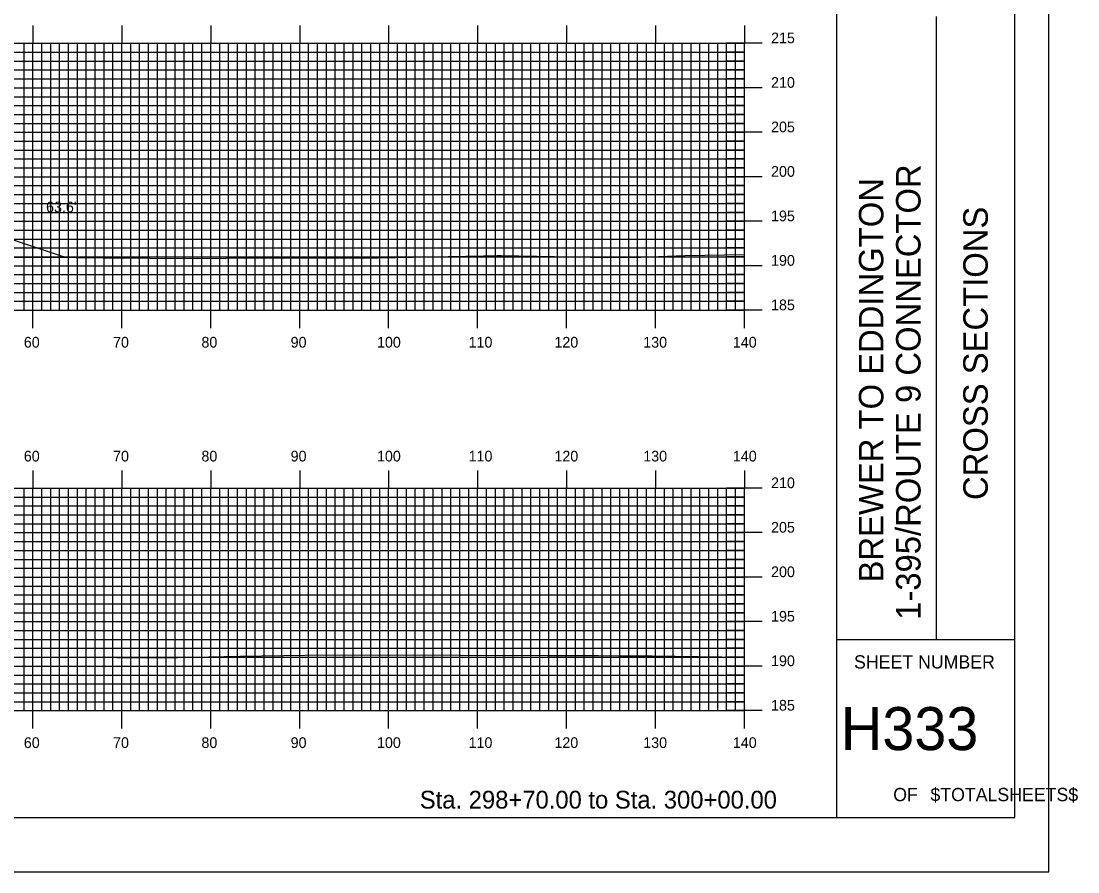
# Model space of a CAD drawing. Extents: x 1815309 to 1815652, y 442591 to 442811.
# Drawn here: x 1815533.2 to 1815652, y 442590.5 to 442686.2 of the extents above; entities that cross this region are included whole.
import ezdxf

# ---------------------------------------------------------------- set-up
doc = ezdxf.new("R2010")
doc.units = 0
for name, color, linetype in [('BORDER', 7, 'Continuous'), ('D_Roadway_Centerline', 7, 'Continuous'), ('D_Roadway_SlopeLines', 7, 'Continuous'), ('D_Text_Standard', 7, 'Continuous'), ('H_V ANNOTATION', 7, 'Continuous'), ('MAJOR', 7, 'Continuous'), ('MINOR', 7, 'Continuous'), ('PLOT BOUNDARY', 7, 'Continuous'), ('S_Roadway_Centerline', 7, 'Continuous')]:
    doc.layers.add(name, color=color, linetype=linetype)

msp = doc.modelspace()

# ---------------------------------------------------------------- linework, layer by layer
at = {"layer": 'BORDER'}
for p, q in [((1815624.93, 442596.67), (1815624.93, 442806.67)), ((1815636.12, 442616.67), (1815636.12, 442686.67)), ((1815624.93, 442616.67), (1815644.93, 442616.67))]:
    msp.add_line(p, q, dxfattribs=at)
msp.add_lwpolyline([(1815324.93, 442596.67), (1815644.93, 442596.67), (1815644.93, 442806.67), (1815324.93, 442806.67)], close=True, dxfattribs=at)
at = {"layer": 'D_Roadway_Centerline'}
msp.add_lwpolyline([(1815410.41, 442660.06), (1815442.53, 442670.77), (1815444.25, 442671.2), (1815454.53, 442673.77), (1815462.53, 442674.06), (1815474.53, 442673.77), (1815486.53, 442673.48), (1815494.53, 442673.16), (1815505.06, 442670.53), (1815506.53, 442670.16), (1815538.16, 442659.62)], dxfattribs=at)
at = {"layer": 'D_Roadway_SlopeLines'}
msp.add_lwpolyline([(1815494.53, 442673.16), (1815506.53, 442670.16), (1815538.16, 442659.62)], dxfattribs=at)
at = {"layer": 'MAJOR'}
for p, q in [((1815534.53, 442685.67), (1815534.53, 442683.67)), ((1815544.53, 442685.67), (1815544.53, 442683.67)), ((1815554.53, 442685.67), (1815554.53, 442683.67)), ((1815564.53, 442685.67), (1815564.53, 442683.67)), ((1815574.53, 442685.67), (1815574.53, 442683.67)), ((1815584.53, 442685.67), (1815584.53, 442683.67)), ((1815594.53, 442685.67), (1815594.53, 442683.67)), ((1815604.53, 442685.67), (1815604.53, 442683.67)), ((1815614.53, 442685.67), (1815614.53, 442683.67)), ((1815334.53, 442683.67), (1815614.53, 442683.67)), ((1815334.53, 442683.67), (1815614.53, 442683.67)), ((1815534.53, 442653.67), (1815534.53, 442683.67)), ((1815544.53, 442653.67), (1815544.53, 442683.67)), ((1815554.53, 442653.67), (1815554.53, 442683.67)), ((1815564.53, 442653.67), (1815564.53, 442683.67)), ((1815574.53, 442653.67), (1815574.53, 442683.67)), ((1815584.53, 442653.67), (1815584.53, 442683.67)), ((1815594.53, 442653.67), (1815594.53, 442683.67)), ((1815604.53, 442653.67), (1815604.53, 442683.67)), ((1815616.54, 442683.67), (1815612.53, 442683.67)), ((1815614.53, 442653.67), (1815614.53, 442683.67)), ((1815614.53, 442653.67), (1815614.53, 442683.67)), ((1815334.53, 442678.67), (1815614.53, 442678.67)), ((1815616.54, 442678.67), (1815612.53, 442678.67)), ((1815334.53, 442673.67), (1815614.53, 442673.67)), ((1815616.54, 442673.67), (1815612.53, 442673.67)), ((1815334.53, 442668.67), (1815614.53, 442668.67)), ((1815616.54, 442668.67), (1815612.53, 442668.67)), ((1815334.53, 442663.67), (1815614.53, 442663.67)), ((1815616.54, 442663.67), (1815612.53, 442663.67)), ((1815334.53, 442658.67), (1815614.53, 442658.67)), ((1815616.54, 442658.67), (1815612.53, 442658.67)), ((1815334.53, 442653.67), (1815614.53, 442653.67)), ((1815334.53, 442653.67), (1815614.53, 442653.67)), ((1815534.53, 442651.66), (1815534.53, 442653.67)), ((1815544.53, 442651.66), (1815544.53, 442653.67)), ((1815554.53, 442651.66), (1815554.53, 442653.67)), ((1815564.53, 442651.66), (1815564.53, 442653.67)), ((1815574.53, 442651.66), (1815574.53, 442653.67)), ((1815584.53, 442651.66), (1815584.53, 442653.67)), ((1815594.53, 442651.66), (1815594.53, 442653.67)), ((1815604.53, 442651.66), (1815604.53, 442653.67)), ((1815616.54, 442653.67), (1815612.53, 442653.67)), ((1815614.53, 442651.66), (1815614.53, 442653.67)), ((1815534.53, 442635.67), (1815534.53, 442633.67)), ((1815544.53, 442635.67), (1815544.53, 442633.67)), ((1815554.53, 442635.67), (1815554.53, 442633.67)), ((1815564.53, 442635.67), (1815564.53, 442633.67)), ((1815574.53, 442635.67), (1815574.53, 442633.67)), ((1815584.53, 442635.67), (1815584.53, 442633.67)), ((1815594.53, 442635.67), (1815594.53, 442633.67)), ((1815604.53, 442635.67), (1815604.53, 442633.67)), ((1815614.53, 442635.67), (1815614.53, 442633.67)), ((1815334.53, 442633.67), (1815614.53, 442633.67)), ((1815334.53, 442633.67), (1815614.53, 442633.67)), ((1815534.53, 442608.67), (1815534.53, 442633.67)), ((1815544.53, 442608.67), (1815544.53, 442633.67)), ((1815554.53, 442608.67), (1815554.53, 442633.67)), ((1815564.53, 442608.67), (1815564.53, 442633.67)), ((1815574.53, 442608.67), (1815574.53, 442633.67)), ((1815584.53, 442608.67), (1815584.53, 442633.67)), ((1815594.53, 442608.67), (1815594.53, 442633.67)), ((1815604.53, 442608.67), (1815604.53, 442633.67)), ((1815616.54, 442633.67), (1815612.53, 442633.67)), ((1815614.53, 442608.67), (1815614.53, 442633.67)), ((1815614.53, 442608.67), (1815614.53, 442633.67)), ((1815334.53, 442628.67), (1815614.53, 442628.67)), ((1815616.54, 442628.67), (1815612.53, 442628.67)), ((1815334.53, 442623.67), (1815614.53, 442623.67)), ((1815616.54, 442623.67), (1815612.53, 442623.67)), ((1815334.53, 442618.67), (1815614.53, 442618.67)), ((1815616.54, 442618.67), (1815612.53, 442618.67)), ((1815334.53, 442613.67), (1815614.53, 442613.67)), ((1815616.54, 442613.67), (1815612.53, 442613.67)), ((1815334.53, 442608.67), (1815614.53, 442608.67)), ((1815334.53, 442608.67), (1815614.53, 442608.67)), ((1815534.53, 442606.66), (1815534.53, 442608.67)), ((1815544.53, 442606.66), (1815544.53, 442608.67)), ((1815554.53, 442606.66), (1815554.53, 442608.67)), ((1815564.53, 442606.66), (1815564.53, 442608.67)), ((1815574.53, 442606.66), (1815574.53, 442608.67)), ((1815584.53, 442606.66), (1815584.53, 442608.67)), ((1815594.53, 442606.66), (1815594.53, 442608.67)), ((1815604.53, 442606.66), (1815604.53, 442608.67)), ((1815616.54, 442608.67), (1815612.53, 442608.67)), ((1815614.53, 442606.66), (1815614.53, 442608.67))]:
    msp.add_line(p, q, dxfattribs=at)
at = {"layer": 'MINOR'}
for p, q in [((1815533.53, 442653.67), (1815533.53, 442683.67)), ((1815535.53, 442653.67), (1815535.53, 442683.67)), ((1815536.53, 442653.67), (1815536.53, 442683.67)), ((1815537.53, 442653.67), (1815537.53, 442683.67)), ((1815538.53, 442653.67), (1815538.53, 442683.67)), ((1815539.53, 442653.67), (1815539.53, 442683.67)), ((1815540.53, 442653.67), (1815540.53, 442683.67)), ((1815541.53, 442653.67), (1815541.53, 442683.67)), ((1815542.53, 442653.67), (1815542.53, 442683.67)), ((1815543.53, 442653.67), (1815543.53, 442683.67)), ((1815545.53, 442653.67), (1815545.53, 442683.67)), ((1815546.53, 442653.67), (1815546.53, 442683.67)), ((1815547.53, 442653.67), (1815547.53, 442683.67)), ((1815548.53, 442653.67), (1815548.53, 442683.67)), ((1815549.53, 442653.67), (1815549.53, 442683.67)), ((1815550.53, 442653.67), (1815550.53, 442683.67)), ((1815551.53, 442653.67), (1815551.53, 442683.67)), ((1815552.53, 442653.67), (1815552.53, 442683.67)), ((1815553.53, 442653.67), (1815553.53, 442683.67)), ((1815555.53, 442653.67), (1815555.53, 442683.67)), ((1815556.53, 442653.67), (1815556.53, 442683.67)), ((1815557.53, 442653.67), (1815557.53, 442683.67)), ((1815558.53, 442653.67), (1815558.53, 442683.67)), ((1815559.53, 442653.67), (1815559.53, 442683.67)), ((1815560.53, 442653.67), (1815560.53, 442683.67)), ((1815561.53, 442653.67), (1815561.53, 442683.67)), ((1815562.53, 442653.67), (1815562.53, 442683.67)), ((1815563.53, 442653.67), (1815563.53, 442683.67)), ((1815565.53, 442653.67), (1815565.53, 442683.67)), ((1815566.53, 442653.67), (1815566.53, 442683.67)), ((1815567.53, 442653.67), (1815567.53, 442683.67)), ((1815568.53, 442653.67), (1815568.53, 442683.67)), ((1815569.53, 442653.67), (1815569.53, 442683.67)), ((1815570.53, 442653.67), (1815570.53, 442683.67)), ((1815571.53, 442653.67), (1815571.53, 442683.67)), ((1815572.53, 442653.67), (1815572.53, 442683.67)), ((1815573.53, 442653.67), (1815573.53, 442683.67)), ((1815575.53, 442653.67), (1815575.53, 442683.67)), ((1815576.53, 442653.67), (1815576.53, 442683.67)), ((1815577.53, 442653.67), (1815577.53, 442683.67)), ((1815578.53, 442653.67), (1815578.53, 442683.67)), ((1815579.53, 442653.67), (1815579.53, 442683.67)), ((1815580.53, 442653.67), (1815580.53, 442683.67)), ((1815581.53, 442653.67), (1815581.53, 442683.67)), ((1815582.53, 442653.67), (1815582.53, 442683.67)), ((1815583.53, 442653.67), (1815583.53, 442683.67)), ((1815585.53, 442653.67), (1815585.53, 442683.67)), ((1815586.53, 442653.67), (1815586.53, 442683.67)), ((1815587.53, 442653.67), (1815587.53, 442683.67)), ((1815588.53, 442653.67), (1815588.53, 442683.67)), ((1815589.53, 442653.67), (1815589.53, 442683.67)), ((1815590.53, 442653.67), (1815590.53, 442683.67)), ((1815591.53, 442653.67), (1815591.53, 442683.67)), ((1815592.53, 442653.67), (1815592.53, 442683.67)), ((1815593.53, 442653.67), (1815593.53, 442683.67)), ((1815595.53, 442653.67), (1815595.53, 442683.67)), ((1815596.53, 442653.67), (1815596.53, 442683.67)), ((1815597.53, 442653.67), (1815597.53, 442683.67)), ((1815598.53, 442653.67), (1815598.53, 442683.67)), ((1815599.53, 442653.67), (1815599.53, 442683.67)), ((1815600.53, 442653.67), (1815600.53, 442683.67)), ((1815601.53, 442653.67), (1815601.53, 442683.67)), ((1815602.53, 442653.67), (1815602.53, 442683.67)), ((1815603.53, 442653.67), (1815603.53, 442683.67)), ((1815605.53, 442653.67), (1815605.53, 442683.67)), ((1815606.53, 442653.67), (1815606.53, 442683.67)), ((1815607.53, 442653.67), (1815607.53, 442683.67)), ((1815608.53, 442653.67), (1815608.53, 442683.67)), ((1815609.53, 442653.67), (1815609.53, 442683.67)), ((1815610.53, 442653.67), (1815610.53, 442683.67)), ((1815611.53, 442653.67), (1815611.53, 442683.67)), ((1815612.53, 442653.67), (1815612.53, 442683.67)), ((1815613.53, 442653.67), (1815613.53, 442683.67)), ((1815334.53, 442682.67), (1815614.53, 442682.67)), ((1815614.53, 442682.67), (1815612.53, 442682.67)), ((1815334.53, 442681.67), (1815614.53, 442681.67)), ((1815614.53, 442681.67), (1815612.53, 442681.67)), ((1815334.53, 442680.67), (1815614.53, 442680.67)), ((1815614.53, 442680.67), (1815612.53, 442680.67)), ((1815334.53, 442679.67), (1815614.53, 442679.67)), ((1815614.53, 442679.67), (1815612.53, 442679.67)), ((1815334.53, 442677.67), (1815614.53, 442677.67)), ((1815614.53, 442677.67), (1815612.53, 442677.67)), ((1815334.53, 442676.67), (1815614.53, 442676.67)), ((1815614.53, 442676.67), (1815612.53, 442676.67)), ((1815334.53, 442675.67), (1815614.53, 442675.67)), ((1815614.53, 442675.67), (1815612.53, 442675.67)), ((1815334.53, 442674.67), (1815614.53, 442674.67)), ((1815614.53, 442674.67), (1815612.53, 442674.67)), ((1815334.53, 442672.67), (1815614.53, 442672.67)), ((1815614.53, 442672.67), (1815612.53, 442672.67)), ((1815334.53, 442671.67), (1815614.53, 442671.67)), ((1815614.53, 442671.67), (1815612.53, 442671.67)), ((1815334.53, 442670.67), (1815614.53, 442670.67)), ((1815614.53, 442670.67), (1815612.53, 442670.67)), ((1815334.53, 442669.67), (1815614.53, 442669.67)), ((1815614.53, 442669.67), (1815612.53, 442669.67)), ((1815334.53, 442667.67), (1815614.53, 442667.67)), ((1815334.53, 442666.67), (1815614.53, 442666.67)), ((1815614.53, 442667.67), (1815612.53, 442667.67)), ((1815614.53, 442666.67), (1815612.53, 442666.67)), ((1815334.53, 442665.67), (1815614.53, 442665.67)), ((1815614.53, 442665.67), (1815612.53, 442665.67)), ((1815334.53, 442664.67), (1815614.53, 442664.67)), ((1815614.53, 442664.67), (1815612.53, 442664.67)), ((1815334.53, 442662.67), (1815614.53, 442662.67)), ((1815614.53, 442662.67), (1815612.53, 442662.67)), ((1815334.53, 442661.67), (1815614.53, 442661.67)), ((1815334.53, 442660.67), (1815614.53, 442660.67)), ((1815614.53, 442661.67), (1815612.53, 442661.67)), ((1815614.53, 442660.67), (1815612.53, 442660.67)), ((1815334.53, 442659.67), (1815614.53, 442659.67)), ((1815614.53, 442659.67), (1815612.53, 442659.67)), ((1815334.53, 442657.67), (1815614.53, 442657.67)), ((1815614.53, 442657.67), (1815612.53, 442657.67)), ((1815334.53, 442656.67), (1815614.53, 442656.67)), ((1815614.53, 442656.67), (1815612.53, 442656.67)), ((1815334.53, 442655.67), (1815614.53, 442655.67)), ((1815614.53, 442655.67), (1815612.53, 442655.67)), ((1815334.53, 442654.67), (1815614.53, 442654.67)), ((1815614.53, 442654.67), (1815612.53, 442654.67)), ((1815533.53, 442608.67), (1815533.53, 442633.67)), ((1815535.53, 442608.67), (1815535.53, 442633.67)), ((1815536.53, 442608.67), (1815536.53, 442633.67)), ((1815537.53, 442608.67), (1815537.53, 442633.67)), ((1815538.53, 442608.67), (1815538.53, 442633.67)), ((1815539.53, 442608.67), (1815539.53, 442633.67)), ((1815540.53, 442608.67), (1815540.53, 442633.67)), ((1815541.53, 442608.67), (1815541.53, 442633.67)), ((1815542.53, 442608.67), (1815542.53, 442633.67)), ((1815543.53, 442608.67), (1815543.53, 442633.67)), ((1815545.53, 442608.67), (1815545.53, 442633.67)), ((1815546.53, 442608.67), (1815546.53, 442633.67)), ((1815547.53, 442608.67), (1815547.53, 442633.67)), ((1815548.53, 442608.67), (1815548.53, 442633.67)), ((1815549.53, 442608.67), (1815549.53, 442633.67)), ((1815550.53, 442608.67), (1815550.53, 442633.67)), ((1815551.53, 442608.67), (1815551.53, 442633.67)), ((1815552.53, 442608.67), (1815552.53, 442633.67)), ((1815553.53, 442608.67), (1815553.53, 442633.67)), ((1815555.53, 442608.67), (1815555.53, 442633.67)), ((1815556.53, 442608.67), (1815556.53, 442633.67)), ((1815557.53, 442608.67), (1815557.53, 442633.67)), ((1815558.53, 442608.67), (1815558.53, 442633.67)), ((1815559.53, 442608.67), (1815559.53, 442633.67)), ((1815560.53, 442608.67), (1815560.53, 442633.67)), ((1815561.53, 442608.67), (1815561.53, 442633.67)), ((1815562.53, 442608.67), (1815562.53, 442633.67)), ((1815563.53, 442608.67), (1815563.53, 442633.67)), ((1815565.53, 442608.67), (1815565.53, 442633.67)), ((1815566.53, 442608.67), (1815566.53, 442633.67)), ((1815567.53, 442608.67), (1815567.53, 442633.67)), ((1815568.53, 442608.67), (1815568.53, 442633.67)), ((1815569.53, 442608.67), (1815569.53, 442633.67)), ((1815570.53, 442608.67), (1815570.53, 442633.67)), ((1815571.53, 442608.67), (1815571.53, 442633.67)), ((1815572.53, 442608.67), (1815572.53, 442633.67)), ((1815573.53, 442608.67), (1815573.53, 442633.67)), ((1815575.53, 442608.67), (1815575.53, 442633.67)), ((1815576.53, 442608.67), (1815576.53, 442633.67)), ((1815577.53, 442608.67), (1815577.53, 442633.67)), ((1815578.53, 442608.67), (1815578.53, 442633.67)), ((1815579.53, 442608.67), (1815579.53, 442633.67)), ((1815580.53, 442608.67), (1815580.53, 442633.67)), ((1815581.53, 442608.67), (1815581.53, 442633.67)), ((1815582.53, 442608.67), (1815582.53, 442633.67)), ((1815583.53, 442608.67), (1815583.53, 442633.67)), ((1815585.53, 442608.67), (1815585.53, 442633.67)), ((1815586.53, 442608.67), (1815586.53, 442633.67)), ((1815587.53, 442608.67), (1815587.53, 442633.67)), ((1815588.53, 442608.67), (1815588.53, 442633.67)), ((1815589.53, 442608.67), (1815589.53, 442633.67)), ((1815590.53, 442608.67), (1815590.53, 442633.67)), ((1815591.53, 442608.67), (1815591.53, 442633.67)), ((1815592.53, 442608.67), (1815592.53, 442633.67)), ((1815593.53, 442608.67), (1815593.53, 442633.67)), ((1815595.53, 442608.67), (1815595.53, 442633.67)), ((1815596.53, 442608.67), (1815596.53, 442633.67)), ((1815597.53, 442608.67), (1815597.53, 442633.67)), ((1815598.53, 442608.67), (1815598.53, 442633.67)), ((1815599.53, 442608.67), (1815599.53, 442633.67)), ((1815600.53, 442608.67), (1815600.53, 442633.67)), ((1815601.53, 442608.67), (1815601.53, 442633.67)), ((1815602.53, 442608.67), (1815602.53, 442633.67)), ((1815603.53, 442608.67), (1815603.53, 442633.67)), ((1815605.53, 442608.67), (1815605.53, 442633.67)), ((1815606.53, 442608.67), (1815606.53, 442633.67)), ((1815607.53, 442608.67), (1815607.53, 442633.67)), ((1815608.53, 442608.67), (1815608.53, 442633.67)), ((1815609.53, 442608.67), (1815609.53, 442633.67)), ((1815610.53, 442608.67), (1815610.53, 442633.67)), ((1815611.53, 442608.67), (1815611.53, 442633.67)), ((1815612.53, 442608.67), (1815612.53, 442633.67)), ((1815613.53, 442608.67), (1815613.53, 442633.67)), ((1815334.53, 442632.67), (1815614.53, 442632.67)), ((1815614.53, 442632.67), (1815612.53, 442632.67)), ((1815334.53, 442631.67), (1815614.53, 442631.67)), ((1815614.53, 442631.67), (1815612.53, 442631.67)), ((1815334.53, 442630.67), (1815614.53, 442630.67)), ((1815614.53, 442630.67), (1815612.53, 442630.67)), ((1815334.53, 442629.67), (1815614.53, 442629.67)), ((1815614.53, 442629.67), (1815612.53, 442629.67)), ((1815334.53, 442627.67), (1815614.53, 442627.67)), ((1815614.53, 442627.67), (1815612.53, 442627.67)), ((1815334.53, 442626.67), (1815614.53, 442626.67)), ((1815614.53, 442626.67), (1815612.53, 442626.67)), ((1815334.53, 442625.67), (1815614.53, 442625.67)), ((1815614.53, 442625.67), (1815612.53, 442625.67)), ((1815334.53, 442624.67), (1815614.53, 442624.67)), ((1815614.53, 442624.67), (1815612.53, 442624.67)), ((1815334.53, 442622.67), (1815614.53, 442622.67)), ((1815614.53, 442622.67), (1815612.53, 442622.67)), ((1815334.53, 442621.67), (1815614.53, 442621.67)), ((1815614.53, 442621.67), (1815612.53, 442621.67)), ((1815334.53, 442620.67), (1815614.53, 442620.67)), ((1815614.53, 442620.67), (1815612.53, 442620.67)), ((1815334.53, 442619.67), (1815614.53, 442619.67)), ((1815614.53, 442619.67), (1815612.53, 442619.67)), ((1815334.53, 442617.67), (1815614.53, 442617.67)), ((1815614.53, 442617.67), (1815612.53, 442617.67)), ((1815334.53, 442616.67), (1815614.53, 442616.67)), ((1815334.53, 442615.67), (1815614.53, 442615.67)), ((1815614.53, 442616.67), (1815612.53, 442616.67)), ((1815614.53, 442615.67), (1815612.53, 442615.67)), ((1815334.53, 442614.67), (1815614.53, 442614.67)), ((1815614.53, 442614.67), (1815612.53, 442614.67)), ((1815334.53, 442612.67), (1815614.53, 442612.67)), ((1815614.53, 442612.67), (1815612.53, 442612.67)), ((1815334.53, 442611.67), (1815614.53, 442611.67)), ((1815614.53, 442611.67), (1815612.53, 442611.67)), ((1815334.53, 442610.67), (1815614.53, 442610.67)), ((1815334.53, 442609.67), (1815614.53, 442609.67)), ((1815614.53, 442610.67), (1815612.53, 442610.67)), ((1815614.53, 442609.67), (1815612.53, 442609.67))]:
    msp.add_line(p, q, dxfattribs=at)
at = {"layer": 'PLOT BOUNDARY'}
msp.add_lwpolyline([(1815308.75, 442590.55), (1815648.75, 442590.55), (1815648.75, 442810.55), (1815308.75, 442810.55)], close=True, dxfattribs=at)
at = {"layer": 'S_Roadway_Centerline'}
for points in [[(1815518.89, 442659.62), (1815536.31, 442659.64), (1815542.44, 442659.56), (1815552.98, 442659.5), (1815559.44, 442659.54), (1815569.87, 442659.55), (1815573.31, 442659.55), (1815585.18, 442659.79), (1815586.74, 442659.82), (1815587.18, 442659.81), (1815599.17, 442659.58), (1815602.87, 442659.64), (1815607.83, 442659.81), (1815614.53, 442659.94)], [(1815532.52, 442614.67), (1815544, 442614.65), (1815549.01, 442614.61), (1815557.8, 442614.8), (1815565.15, 442614.89), (1815577.28, 442614.92), (1815582.62, 442614.9), (1815592.41, 442614.88), (1815598.14, 442614.87), (1815600.4, 442614.83), (1815604.18, 442614.82), (1815614.53, 442614.66)]]:
    msp.add_lwpolyline(points, dxfattribs=at)

# ---------------------------------------------------------------- texts
at = {"layer": 'BORDER'}
for s, p in [('1-395/ROUTE 9 CONNECTOR', (1815634.34, 442618.87)), ('BREWER TO EDDINGTON', (1815630.16, 442623.07)), ('CROSS SECTIONS', (1815641.9, 442632.34))]:
    msp.add_text(s, height=2.7557, rotation=90, dxfattribs=at).set_placement(p)
for s, height, p in [('SHEET NUMBER', 1.4905, (1815626.86, 442613.4)), ('H333', 4.839, (1815625.37, 442604.23)), ('$TOTALSHEETS$', 1.4905, (1815635.45, 442598.49)), ('OF', 1.491, (1815631.27, 442598.49))]:
    msp.add_text(s, height=height, dxfattribs=at).set_placement(p)
at = {"layer": 'D_Text_Standard'}
msp.add_text("63.6'", height=1.2, dxfattribs=at).set_placement((1815536.01, 442664.67))
at = {"layer": 'H_V ANNOTATION'}
for s, height, p in [('215', 1.2, (1815617.53, 442683.67)), ('210', 1.2, (1815617.53, 442678.67)), ('205', 1.2, (1815617.53, 442673.67)), ('200', 1.2, (1815617.53, 442668.67)), ('195', 1.2, (1815617.53, 442663.67)), ('190', 1.2, (1815617.53, 442658.67)), ('185', 1.2, (1815617.53, 442653.67)), ('60', 1.2, (1815533.51, 442649.47)), ('70', 1.2, (1815543.54, 442649.47)), ('80', 1.2, (1815553.48, 442649.47)), ('90', 1.2, (1815563.51, 442649.47)), ('100', 1.2, (1815573.22, 442649.47)), ('110', 1.2, (1815583.52, 442649.47)), ('120', 1.2, (1815593.17, 442649.47)), ('130', 1.2, (1815603.16, 442649.47)), ('140', 1.2, (1815613.24, 442649.47)), ('60', 1.2, (1815533.51, 442636.67)), ('70', 1.2, (1815543.54, 442636.67)), ('80', 1.2, (1815553.48, 442636.67)), ('90', 1.2, (1815563.51, 442636.67)), ('100', 1.2, (1815573.22, 442636.67)), ('110', 1.2, (1815583.52, 442636.67)), ('120', 1.2, (1815593.17, 442636.67)), ('130', 1.2, (1815603.16, 442636.67)), ('140', 1.2, (1815613.24, 442636.67)), ('210', 1.2, (1815617.53, 442633.67)), ('205', 1.2, (1815617.53, 442628.67)), ('200', 1.2, (1815617.53, 442623.67)), ('195', 1.2, (1815617.53, 442618.67)), ('190', 1.2, (1815617.53, 442613.67)), ('185', 1.2, (1815617.53, 442608.67)), ('60', 1.2, (1815533.51, 442604.47)), ('70', 1.2, (1815543.54, 442604.47)), ('80', 1.2, (1815553.48, 442604.47)), ('90', 1.2, (1815563.51, 442604.47)), ('100', 1.2, (1815573.22, 442604.47)), ('110', 1.2, (1815583.52, 442604.47)), ('120', 1.2, (1815593.17, 442604.47)), ('130', 1.2, (1815603.16, 442604.47)), ('140', 1.2, (1815613.24, 442604.47)), ('Sta. 298+70.00 to Sta. 300+00.00', 2.0004, (1815578.03, 442597.66))]:
    msp.add_text(s, height=height, dxfattribs=at).set_placement(p)

doc.saveas('drawing.dxf')
